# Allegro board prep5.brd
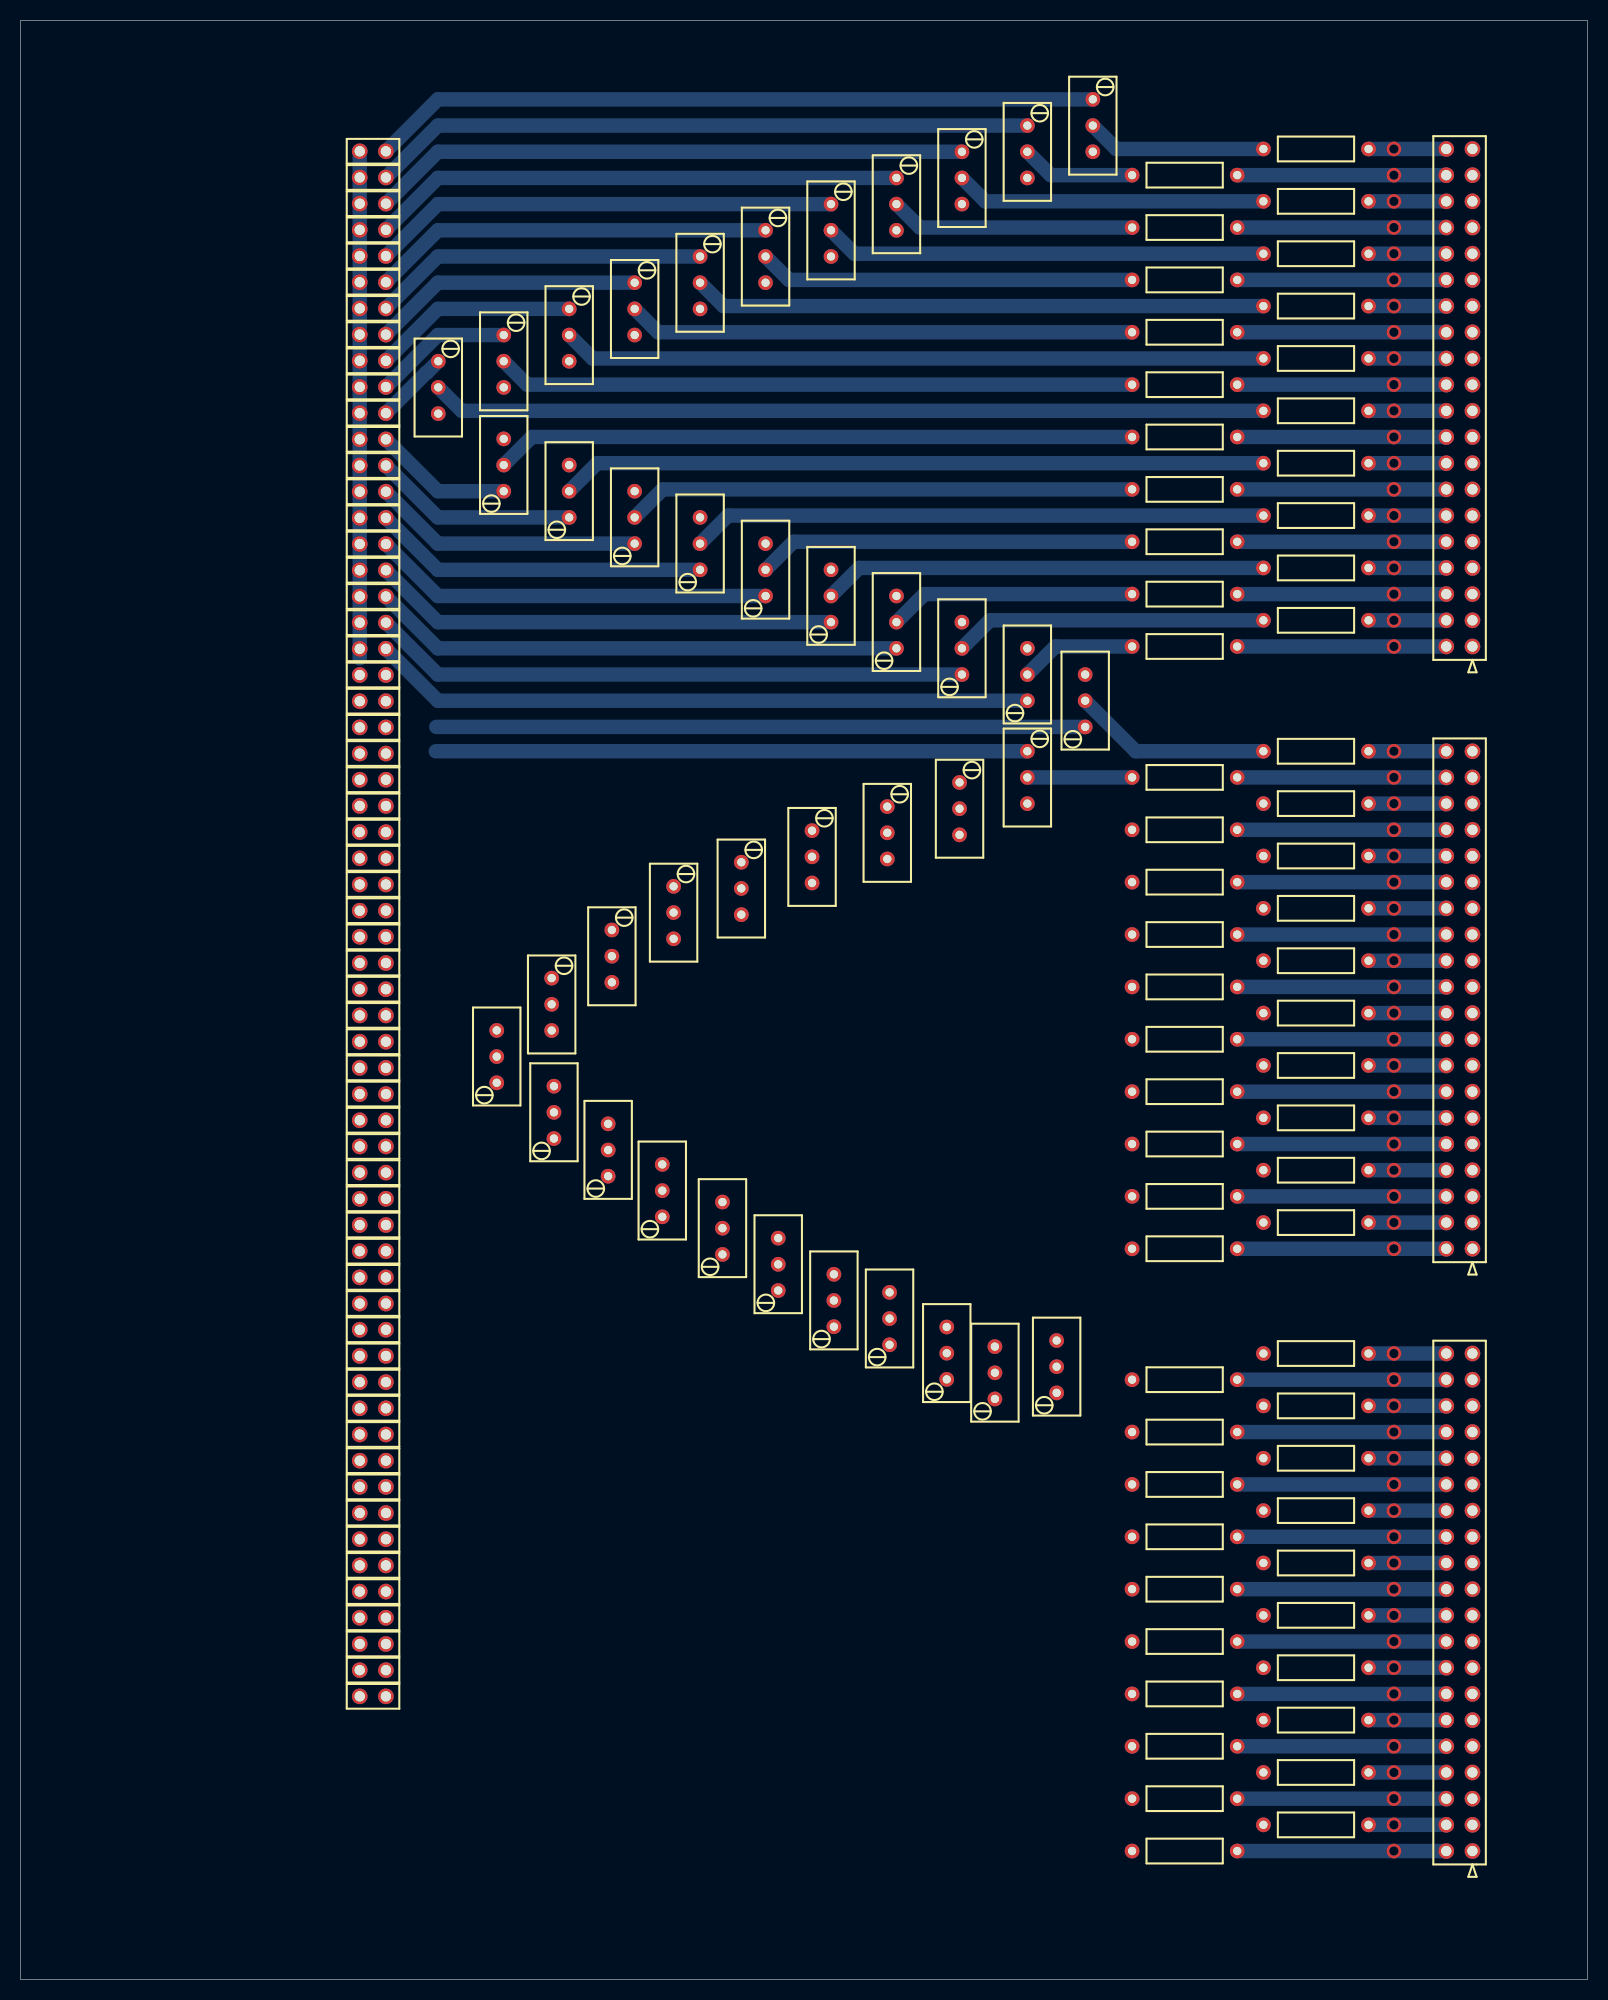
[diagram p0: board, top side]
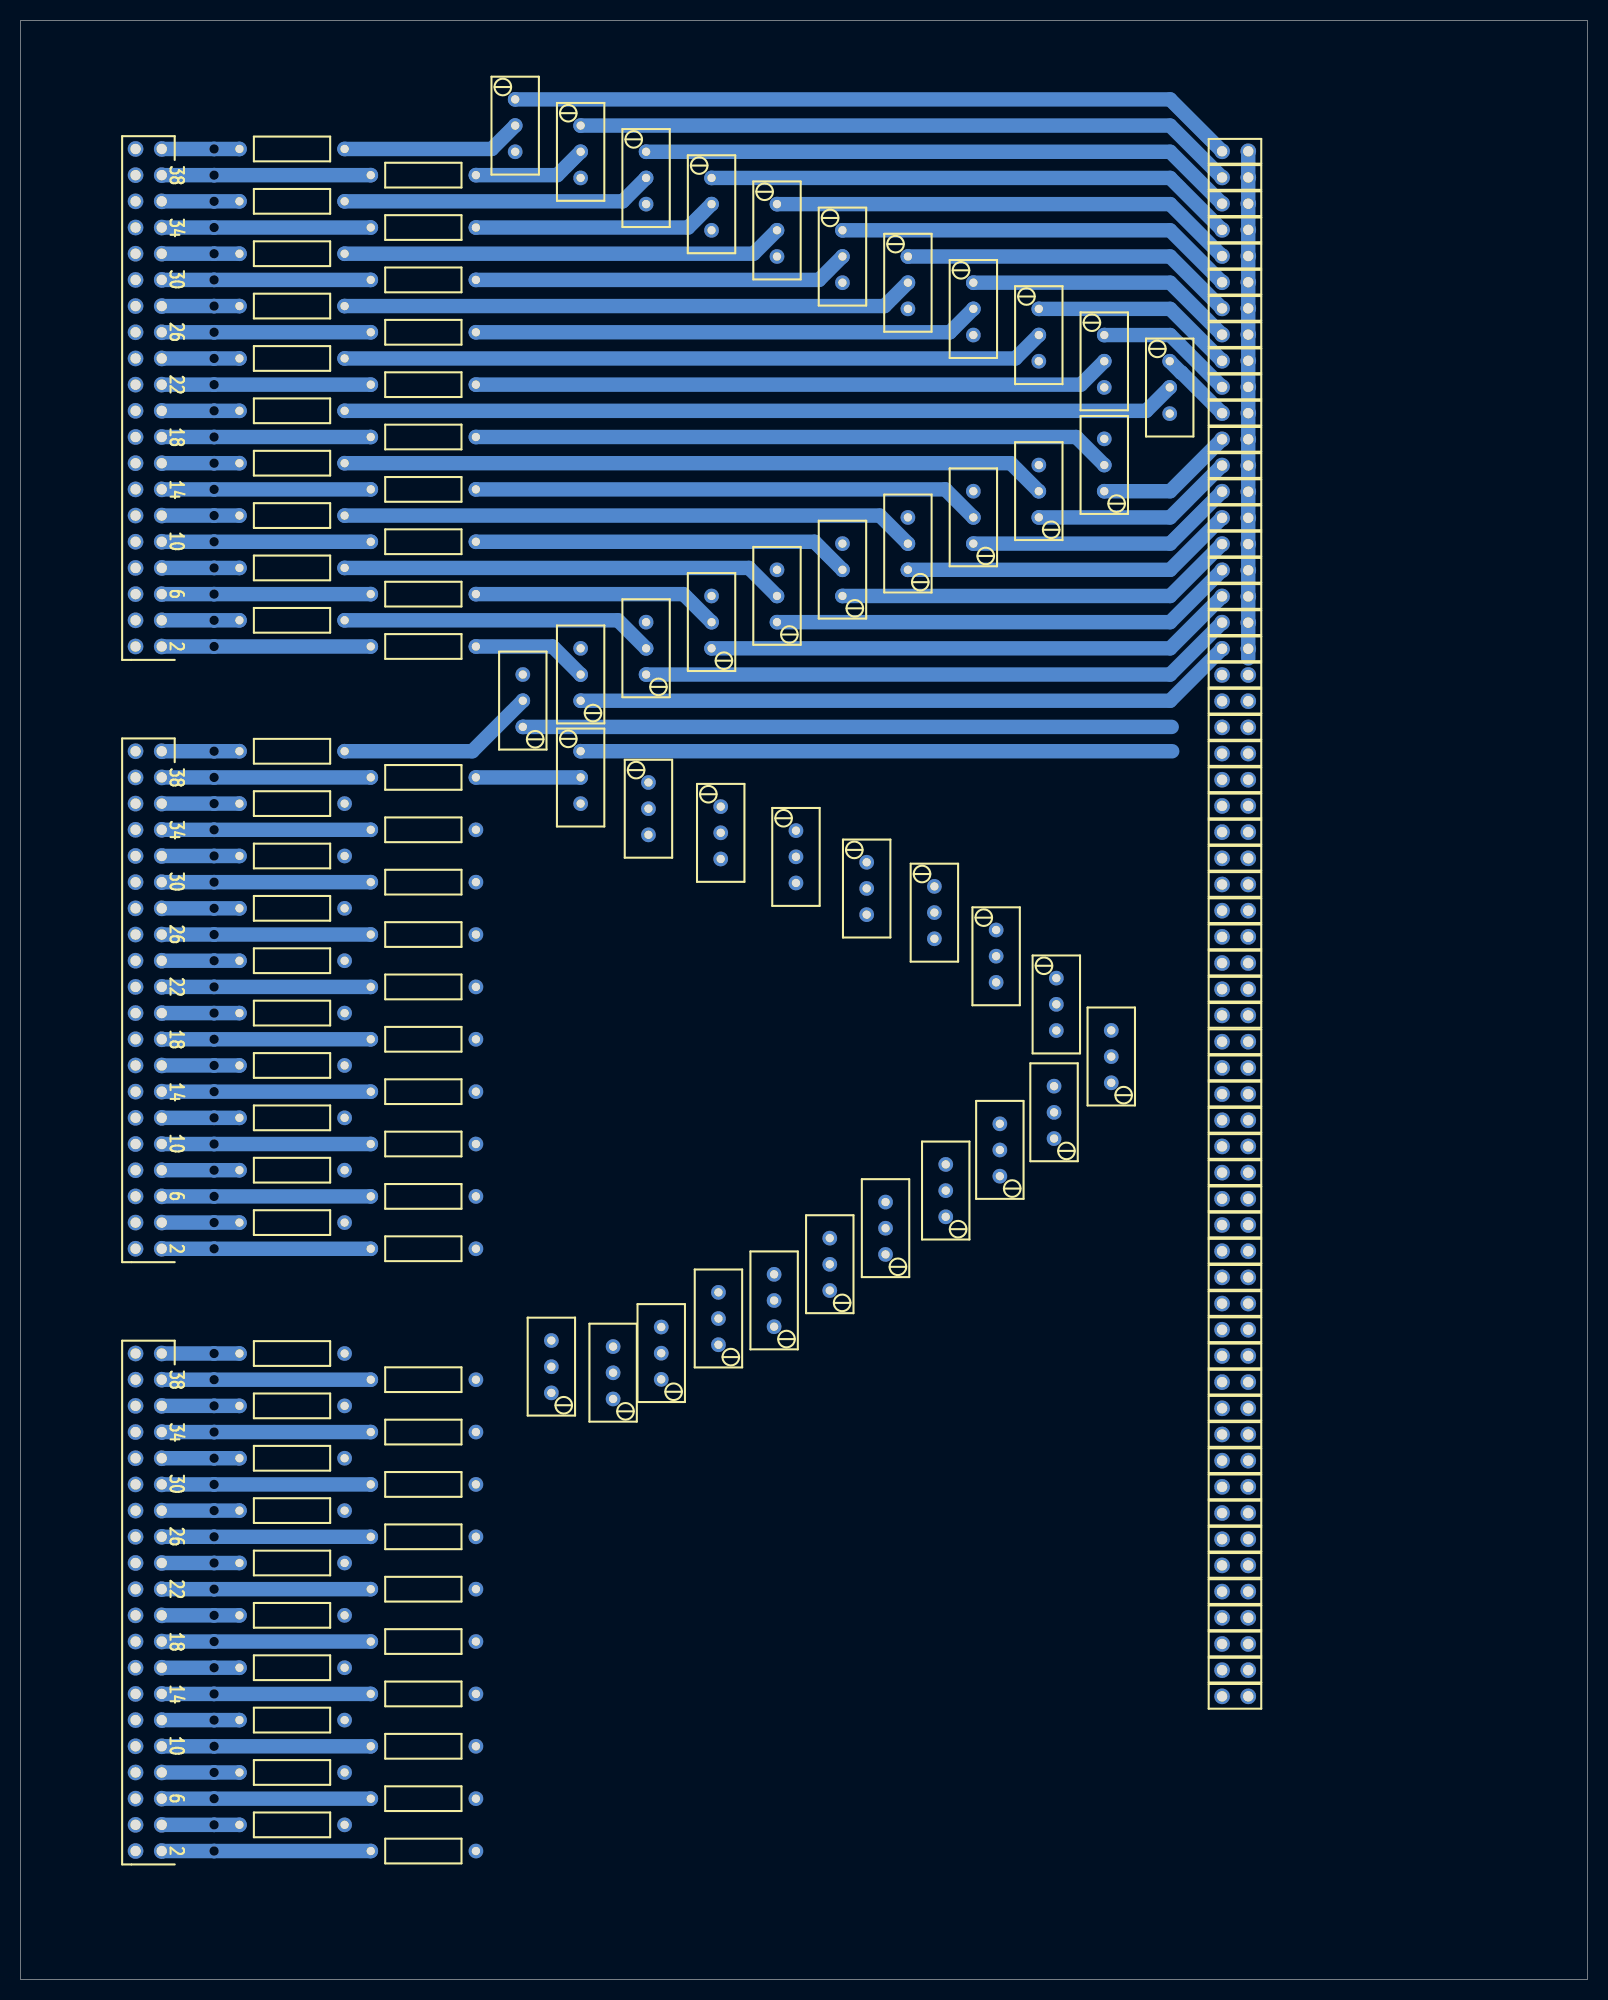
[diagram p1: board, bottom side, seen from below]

Outline 152 x 190 mm; copper layers: TOP, BOTTOM. Coordinates in mm from the lower left corner of the outline.
Outline path: 0,190 152,190 152,0 0,0 0,190

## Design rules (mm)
constraint set DEFAULT: min track width 0.15, pair gap 0.15

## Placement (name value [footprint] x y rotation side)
J1  -  [CONHE13D2X20M]  140.85 129.29 0 top
J2  -  [CONHE13D2X20M]  140.85 70.87 0 top
J3  -  [CONHE13D2X20M]  140.85 12.45 0 top
NOREF  -  []  0 0 90 top
NOREF#2  -  []  0 0 0 top
PO1  100  [POT45X95D]  104.02 182.36 270 top
PO2  100  [POT45X95D]  97.67 179.82 270 top
PO3  100  [POT45X95D]  91.32 177.28 270 top
PO4  100  [POT45X95D]  84.97 174.74 270 top
PO5  100  [POT45X95D]  78.62 172.2 270 top
PO6  100  [POT45X95D]  72.27 169.66 270 top
PO7  100  [POT45X95D]  65.92 167.12 270 top
PO8  100  [POT45X95D]  59.57 164.58 270 top
PO9  100  [POT45X95D]  53.22 162.04 270 top
PO10  100  [POT45X95D]  46.87 159.5 270 top
PO11  100  [POT45X95D]  40.52 156.96 270 top
PO12  100  [POT45X95D]  46.87 144.35 90 top
PO13  100  [POT45X95D]  53.22 141.81 90 top
PO14  100  [POT45X95D]  59.57 139.27 90 top
PO15  100  [POT45X95D]  65.92 136.73 90 top
PO16  100  [POT45X95D]  72.27 134.19 90 top
PO17  100  [POT45X95D]  78.62 131.65 90 top
PO18  100  [POT45X95D]  84.97 129.11 90 top
PO19  100  [POT45X95D]  91.32 126.57 90 top
PO20  100  [POT45X95D]  97.67 124.03 90 top
PO21  100  [POT45X95D]  103.28 121.49 90 top
PO22  100  [POT45X95D]  97.67 119.13 270 top
PO23  100  [POT45X95D]  91.09 116.1 270 top
PO24  100  [POT45X95D]  84.08 113.76 270 top
PO25  100  [POT45X95D]  76.78 111.43 270 top
PO26  100  [POT45X95D]  69.92 108.36 270 top
PO27  100  [POT45X95D]  63.35 106.02 270 top
PO28  100  [POT45X95D]  57.36 101.79 270 top
PO29  100  [POT45X95D]  51.52 97.12 270 top
PO30  100  [POT45X95D]  46.19 86.97 90 top
PO31  100  [POT45X95D]  51.74 81.56 90 top
PO32  100  [POT45X95D]  57 77.91 90 top
PO33  100  [POT45X95D]  62.25 73.97 90 top
PO34  100  [POT45X95D]  68.09 70.32 90 top
PO35  100  [POT45X95D]  73.5 66.82 90 top
PO36  100  [POT45X95D]  78.9 63.31 90 top
PO37  100  [POT45X95D]  84.3 61.56 90 top
PO38  100  [POT45X95D]  89.85 58.2 90 top
PO39  100  [POT45X95D]  94.52 56.3 90 top
PO40  100  [POT45X95D]  100.51 56.89 90 top
R1  100  [R100]  130.77 177.55 180 top
R2  100  [R100]  118.03 175.01 180 top
R3  100  [R100]  130.77 172.47 180 top
R4  100  [R100]  118.03 169.93 180 top
R5  100  [R100]  130.77 167.39 180 top
R6  100  [R100]  118.03 164.85 180 top
R7  100  [R100]  130.77 162.31 180 top
R8  100  [R100]  118.03 159.77 180 top
R9  100  [R100]  130.77 157.23 180 top
R10  100  [R100]  118.03 154.69 180 top
R11  100  [R100]  130.77 152.15 180 top
R12  100  [R100]  118.03 149.61 180 top
R13  100  [R100]  130.77 147.07 180 top
R14  100  [R100]  118.03 144.53 180 top
R15  100  [R100]  130.77 141.99 180 top
R16  100  [R100]  118.03 139.45 180 top
R17  100  [R100]  130.77 136.91 180 top
R18  100  [R100]  118.03 134.37 180 top
R19  100  [R100]  130.77 131.83 180 top
R20  100  [R100]  118.03 129.29 180 top
R21  100  [R100]  130.77 119.13 180 top
R22  100  [R100]  118.03 116.59 180 top
R23  100  [R100]  130.77 114.05 180 top
R24  100  [R100]  118.03 111.51 180 top
R25  100  [R100]  130.77 108.97 180 top
R26  100  [R100]  118.03 106.43 180 top
R27  100  [R100]  130.77 103.89 180 top
R28  100  [R100]  118.03 101.35 180 top
R29  100  [R100]  130.77 98.81 180 top
R30  100  [R100]  118.03 96.27 180 top
R31  100  [R100]  130.77 93.73 180 top
R32  100  [R100]  118.03 91.19 180 top
R33  100  [R100]  130.77 88.65 180 top
R34  100  [R100]  118.03 86.11 180 top
R35  100  [R100]  130.77 83.57 180 top
R36  100  [R100]  118.03 81.03 180 top
R37  100  [R100]  130.77 78.49 180 top
R38  100  [R100]  118.03 75.95 180 top
R39  100  [R100]  130.77 73.41 180 top
R40  100  [R100]  118.03 70.87 180 top
R41  100  [R100]  130.77 60.71 180 top
R42  100  [R100]  118.03 58.17 180 top
R43  100  [R100]  130.77 55.63 180 top
R44  100  [R100]  118.03 53.09 180 top
R45  100  [R100]  130.77 50.55 180 top
R46  100  [R100]  118.03 48.01 180 top
R47  100  [R100]  130.77 45.47 180 top
R48  100  [R100]  118.03 42.93 180 top
R49  100  [R100]  130.77 40.39 180 top
R50  100  [R100]  118.03 37.85 180 top
R51  100  [R100]  130.77 35.31 180 top
R52  100  [R100]  118.03 32.77 180 top
R53  100  [R100]  130.77 30.23 180 top
R54  100  [R100]  118.03 27.69 180 top
R55  100  [R100]  130.77 25.15 180 top
R56  100  [R100]  118.03 22.61 180 top
R57  100  [R100]  130.77 20.07 180 top
R58  100  [R100]  118.03 17.53 180 top
R59  100  [R100]  130.77 14.99 180 top
R60  100  [R100]  118.03 12.45 180 top
S1  -  [CONHE13D2M]  35.44 177.32 180 top
S2  -  [CONHE13D2M]  35.44 174.78 180 top
S3  -  [CONHE13D2M]  35.44 172.25 180 top
S4  -  [CONHE13D2M]  35.44 169.71 180 top
S5  -  [CONHE13D2M]  35.44 167.16 180 top
S6  -  [CONHE13D2M]  35.44 164.62 180 top
S7  -  [CONHE13D2M]  35.44 162.09 180 top
S8  -  [CONHE13D2M]  35.44 159.54 180 top
S9  -  [CONHE13D2M]  35.44 157 180 top
S10  -  [CONHE13D2M]  35.44 154.47 180 top
S11  -  [CONHE13D2M]  35.44 151.93 180 top
S12  -  [CONHE13D2M]  35.44 149.38 180 top
S13  -  [CONHE13D2M]  35.44 146.84 180 top
S14  -  [CONHE13D2M]  35.44 144.31 180 top
S15  -  [CONHE13D2M]  35.44 141.76 180 top
S16  -  [CONHE13D2M]  35.44 139.22 180 top
S17  -  [CONHE13D2M]  35.44 136.69 180 top
S18  -  [CONHE13D2M]  35.44 134.15 180 top
S19  -  [CONHE13D2M]  35.44 131.6 180 top
S20  -  [CONHE13D2M]  35.44 129.06 180 top
S21  -  [CONHE13D2M]  35.44 126.53 180 top
S22  -  [CONHE13D2M]  35.44 123.98 180 top
S23  -  [CONHE13D2M]  35.44 121.44 180 top
S24  -  [CONHE13D2M]  35.44 118.91 180 top
S25  -  [CONHE13D2M]  35.44 116.36 180 top
S26  -  [CONHE13D2M]  35.44 113.83 180 top
S27  -  [CONHE13D2M]  35.44 111.28 180 top
S28  -  [CONHE13D2M]  35.44 108.75 180 top
S29  -  [CONHE13D2M]  35.44 106.2 180 top
S30  -  [CONHE13D2M]  35.44 103.67 180 top
S31  -  [CONHE13D2M]  35.44 101.12 180 top
S32  -  [CONHE13D2M]  35.44 98.58 180 top
S33  -  [CONHE13D2M]  35.44 96.05 180 top
S34  -  [CONHE13D2M]  35.44 93.5 180 top
S35  -  [CONHE13D2M]  35.44 90.95 180 top
S36  -  [CONHE13D2M]  35.44 88.42 180 top
S37  -  [CONHE13D2M]  35.44 85.88 180 top
S38  -  [CONHE13D2M]  35.44 83.33 180 top
S39  -  [CONHE13D2M]  35.44 80.8 180 top
S40  -  [CONHE13D2M]  35.44 78.25 180 top
S41  -  [CONHE13D2M]  35.44 75.72 180 top
S42  -  [CONHE13D2M]  35.44 73.17 180 top
S43  -  [CONHE13D2M]  35.44 70.64 180 top
S44  -  [CONHE13D2M]  35.44 68.09 180 top
S45  -  [CONHE13D2M]  35.44 65.56 180 top
S46  -  [CONHE13D2M]  35.44 63.02 180 top
S47  -  [CONHE13D2M]  35.44 60.48 180 top
S48  -  [CONHE13D2M]  35.44 57.94 180 top
S49  -  [CONHE13D2M]  35.44 55.4 180 top
S50  -  [CONHE13D2M]  35.44 52.85 180 top
S51  -  [CONHE13D2M]  35.44 50.31 180 top
S52  -  [CONHE13D2M]  35.44 47.77 180 top
S53  -  [CONHE13D2M]  35.44 45.23 180 top
S54  -  [CONHE13D2M]  35.44 42.7 180 top
S55  -  [CONHE13D2M]  35.44 40.16 180 top
S56  -  [CONHE13D2M]  35.44 37.62 180 top
S57  -  [CONHE13D2M]  35.44 35.08 180 top
S58  -  [CONHE13D2M]  35.44 32.53 180 top
S59  -  [CONHE13D2M]  35.44 30 180 top
S60  -  [CONHE13D2M]  35.44 27.45 180 top

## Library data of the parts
J1-J3 = CON40P: part number: CON40P-HE13D
PO1-PO40 = POT: part number: POT-100,1/2W20T_D
R1-R60 = RGEN: part number: RGEN-100,M500MW5%
S1-S60 = STRAP: part number: STRAP-2X1

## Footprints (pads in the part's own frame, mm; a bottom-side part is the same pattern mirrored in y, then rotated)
CONHE13D2M
  round 1.52 hole 1: 1(0,0) 2(2.54,0)
CONHE13D2X20M
  round 1.52 hole 1: 1(0,0) 2(-2.54,0) 3(0,2.54) 4(-2.54,2.54) 5(0,5.08) 6(-2.54,5.08) 7(0,7.62) 8(-2.54,7.62) 9(0,10.16) 10(-2.54,10.16) 11(0,12.7) 12(-2.54,12.7) 13(0,15.24) 14(-2.54,15.24) 15(0,17.78) 16(-2.54,17.78) 17(0,20.32) 18(-2.54,20.32) 19(0,22.86) 20(-2.54,22.86) 21(0,25.4) 22(-2.54,25.4) 23(0,27.94) 24(-2.54,27.94) 25(0,30.48) 26(-2.54,30.48) 27(0,33.02) 28(-2.54,33.02) 29(0,35.56) 30(-2.54,35.56) 31(0,38.1) 32(-2.54,38.1) 33(0,40.64) 34(-2.54,40.64) 35(0,43.18) 36(-2.54,43.18) 37(0,45.72) 38(-2.54,45.72) 39(0,48.26) 40(-2.54,48.26)
POT45X95D
  round 1.43 hole 0.8: 1(0,0) 2(2.54,0) 3(5.08,0)
R100
  round 1.43 hole 0.8: 1(0,0) 2(10.2,0)

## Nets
GND: J1.1 J1.3 J1.5 J1.7 J1.9 J1.11 J1.13 J1.15 J1.17 J1.19 J1.21 J1.23 J1.25 J1.27 J1.29 J1.31 J1.33 J1.35 J1.37 J1.39 J2.1 J2.3 J2.5 J2.7 J2.9 J2.11 J2.13 J2.15 J2.17 J2.19 J2.21 J2.23 J2.25 J2.27 J2.29 J2.31 J2.33 J2.35 J2.37 J2.39 J3.1 J3.3 J3.5 J3.7 J3.9 J3.11 J3.13 J3.15 J3.17 J3.19 J3.21 J3.23 J3.25 J3.27 J3.29 J3.31 J3.33 J3.35 J3.37 J3.39
UNNAMED_1_CON40P_I1_A: J1.10(A<9>) R16.1
UNNAMED_1_CON40P_I1_A_1: J1.8 R17.1
UNNAMED_1_CON40P_I1_A_2: J1.6 R18.1
UNNAMED_1_CON40P_I1_A_3: J1.4 R19.1
UNNAMED_1_CON40P_I1_A_4: J1.40 R1.1
UNNAMED_1_CON40P_I1_A_5: J1.38 R2.1
UNNAMED_1_CON40P_I1_A_6: J1.36 R3.1
UNNAMED_1_CON40P_I1_A_7: J1.34 R4.1
UNNAMED_1_CON40P_I1_A_8: J1.32 R5.1
UNNAMED_1_CON40P_I1_A_9: J1.30 R6.1
UNNAMED_1_CON40P_I1_A_10: J1.28 R7.1
UNNAMED_1_CON40P_I1_A_11: J1.26 R8.1
UNNAMED_1_CON40P_I1_A_12: J1.24 R9.1
UNNAMED_1_CON40P_I1_A_13: J1.22 R10.1
UNNAMED_1_CON40P_I1_A_14: J1.2 R20.1
UNNAMED_1_CON40P_I1_A_15: J1.20 R11.1
UNNAMED_1_CON40P_I1_A_16: J1.18 R12.1
UNNAMED_1_CON40P_I1_A_17: J1.16 R13.1
UNNAMED_1_CON40P_I1_A_18: J1.14 R14.1
UNNAMED_1_CON40P_I1_A_19: J1.12 R15.1
UNNAMED_1_CON40P_I2_A: J3.28 R47.1
UNNAMED_1_CON40P_I2_A_1: J3.30 R46.1
UNNAMED_1_CON40P_I2_A_2: J3.38 R42.1
UNNAMED_1_CON40P_I2_A_3: J3.32 R45.1
UNNAMED_1_CON40P_I2_A_4: J3.34 R44.1
UNNAMED_1_CON40P_I2_A_5: J3.36 R43.1
UNNAMED_1_CON40P_I2_A_6: J3.40 R41.1
UNNAMED_1_CON40P_I2_A_7: J3.6 R58.1
UNNAMED_1_CON40P_I2_A_8: J3.8 R57.1
UNNAMED_1_CON40P_I2_A_9: J3.4 R59.1
UNNAMED_1_CON40P_I2_A_10: J3.2 R60.1
UNNAMED_1_CON40P_I2_A_11: J3.10(A<9>) R56.1
UNNAMED_1_CON40P_I2_A_12: J3.12 R55.1
UNNAMED_1_CON40P_I2_A_13: J3.14 R54.1
UNNAMED_1_CON40P_I2_A_14: J3.16 R53.1
UNNAMED_1_CON40P_I2_A_15: J3.18 R52.1
UNNAMED_1_CON40P_I2_A_16: J3.20 R51.1
UNNAMED_1_CON40P_I2_A_17: J3.22 R50.1
UNNAMED_1_CON40P_I2_A_18: J3.24 R49.1
UNNAMED_1_CON40P_I2_A_19: J3.26 R48.1
UNNAMED_1_CON40P_I3_A: J2.28 R27.1
UNNAMED_1_CON40P_I3_A_1: J2.30 R26.1
UNNAMED_1_CON40P_I3_A_2: J2.38 R22.1
UNNAMED_1_CON40P_I3_A_3: J2.32 R25.1
UNNAMED_1_CON40P_I3_A_4: J2.34 R24.1
UNNAMED_1_CON40P_I3_A_5: J2.36 R23.1
UNNAMED_1_CON40P_I3_A_6: J2.40 R21.1
UNNAMED_1_CON40P_I3_A_7: J2.6 R38.1
UNNAMED_1_CON40P_I3_A_8: J2.8 R37.1
UNNAMED_1_CON40P_I3_A_9: J2.4 R39.1
UNNAMED_1_CON40P_I3_A_10: J2.2 R40.1
UNNAMED_1_CON40P_I3_A_11: J2.10(A<9>) R36.1
UNNAMED_1_CON40P_I3_A_12: J2.12 R35.1
UNNAMED_1_CON40P_I3_A_13: J2.14 R34.1
UNNAMED_1_CON40P_I3_A_14: J2.16 R33.1
UNNAMED_1_CON40P_I3_A_15: J2.18 R32.1
UNNAMED_1_CON40P_I3_A_16: J2.20 R31.1
UNNAMED_1_CON40P_I3_A_17: J2.22 R30.1
UNNAMED_1_CON40P_I3_A_18: J2.24 R29.1
UNNAMED_1_CON40P_I3_A_19: J2.26 R28.1
UNNAMED_1_POT_I5_A: PO1.1 S1.1
UNNAMED_1_POT_I5_B: PO1.2 R1.2(B<0>)
UNNAMED_1_POT_I7_A: PO2.1 S2.1
UNNAMED_1_POT_I7_B: PO2.2 R2.2(B<0>)
UNNAMED_1_POT_I26_A: PO3.1 S3.1
UNNAMED_1_POT_I26_B: PO3.2 R3.2(B<0>)
UNNAMED_1_POT_I27_A: PO4.1 S4.1
UNNAMED_1_POT_I27_B: PO4.2 R4.2(B<0>)
UNNAMED_1_POT_I28_A: PO5.1 S5.1
UNNAMED_1_POT_I28_B: PO5.2 R5.2(B<0>)
UNNAMED_1_POT_I29_A: PO6.1 S6.1
UNNAMED_1_POT_I29_B: PO6.2 R6.2(B<0>)
UNNAMED_1_POT_I30_A: PO7.1 S7.1
UNNAMED_1_POT_I30_B: PO7.2 R7.2(B<0>)
UNNAMED_1_POT_I31_A: PO8.1 S8.1
UNNAMED_1_POT_I31_B: PO8.2 R8.2(B<0>)
UNNAMED_1_POT_I32_A: PO9.1 S9.1
UNNAMED_1_POT_I32_B: PO9.2 R9.2(B<0>)
UNNAMED_1_POT_I33_A: PO10.1 S10.1
UNNAMED_1_POT_I33_B: PO10.2 R10.2(B<0>)
UNNAMED_1_POT_I34_A: PO11.1 S11.1
UNNAMED_1_POT_I34_B: PO11.2 R11.2(B<0>)
UNNAMED_1_POT_I35_A: PO12.1 S12.1
UNNAMED_1_POT_I35_B: PO12.2 R12.2(B<0>)
UNNAMED_1_POT_I36_A: PO13.1 S13.1
UNNAMED_1_POT_I36_B: PO13.2 R13.2(B<0>)
UNNAMED_1_POT_I37_A: PO14.1 S14.1
UNNAMED_1_POT_I37_B: PO14.2 R14.2(B<0>)
UNNAMED_1_POT_I38_A: PO15.1 S15.1
UNNAMED_1_POT_I38_B: PO15.2 R15.2(B<0>)
UNNAMED_1_POT_I39_A: PO16.1 S16.1
UNNAMED_1_POT_I39_B: PO16.2 R16.2(B<0>)
UNNAMED_1_POT_I40_A: PO17.1 S17.1
UNNAMED_1_POT_I40_B: PO17.2 R17.2(B<0>)
UNNAMED_1_POT_I41_A: PO18.1 S18.1
UNNAMED_1_POT_I41_B: PO18.2 R18.2(B<0>)
UNNAMED_1_POT_I42_A: PO19.1 S19.1
UNNAMED_1_POT_I42_B: PO19.2 R19.2(B<0>)
UNNAMED_1_POT_I43_A: PO20.1 S20.1
UNNAMED_1_POT_I43_B: PO20.2 R20.2(B<0>)
UNNAMED_1_POT_I44_A: PO40.1 S40.1
UNNAMED_1_POT_I44_B: PO40.2 R40.2(B<0>)
UNNAMED_1_POT_I45_A: PO39.1 S39.1
UNNAMED_1_POT_I45_B: PO39.2 R39.2(B<0>)
UNNAMED_1_POT_I46_A: PO38.1 S38.1
UNNAMED_1_POT_I46_B: PO38.2 R38.2(B<0>)
UNNAMED_1_POT_I47_A: PO33.1 S33.1
UNNAMED_1_POT_I47_B: PO33.2 R33.2(B<0>)
UNNAMED_1_POT_I48_A: PO32.1 S32.1
UNNAMED_1_POT_I48_B: PO32.2 R32.2(B<0>)
UNNAMED_1_POT_I49_A: PO31.1 S31.1
UNNAMED_1_POT_I49_B: PO31.2 R31.2(B<0>)
UNNAMED_1_POT_I50_A: PO30.1 S30.1
UNNAMED_1_POT_I50_B: PO30.2 R30.2(B<0>)
UNNAMED_1_POT_I51_A: PO29.1 S29.1
UNNAMED_1_POT_I51_B: PO29.2 R29.2(B<0>)
UNNAMED_1_POT_I52_A: PO27.1 S27.1
UNNAMED_1_POT_I52_B: PO27.2 R27.2(B<0>)
UNNAMED_1_POT_I53_A: PO28.1 S28.1
UNNAMED_1_POT_I53_B: PO28.2 R28.2(B<0>)
UNNAMED_1_POT_I54_A: PO26.1 S26.1
UNNAMED_1_POT_I54_B: PO26.2 R26.2(B<0>)
UNNAMED_1_POT_I55_A: PO25.1 S25.1
UNNAMED_1_POT_I55_B: PO25.2 R25.2(B<0>)
UNNAMED_1_POT_I56_A: PO24.1 S24.1
UNNAMED_1_POT_I56_B: PO24.2 R24.2(B<0>)
UNNAMED_1_POT_I57_A: PO22.1 S22.1
UNNAMED_1_POT_I57_B: PO22.2 R22.2(B<0>)
UNNAMED_1_POT_I58_A: PO21.1 S21.1
UNNAMED_1_POT_I58_B: PO21.2 R21.2(B<0>)
UNNAMED_1_POT_I59_A: PO23.1 S23.1
UNNAMED_1_POT_I59_B: PO23.2 R23.2(B<0>)
UNNAMED_1_POT_I72_A: PO37.1 S37.1
UNNAMED_1_POT_I72_B: PO37.2 R37.2(B<0>)
UNNAMED_1_POT_I73_A: PO36.1 S36.1
UNNAMED_1_POT_I73_B: PO36.2 R36.2(B<0>)
UNNAMED_1_POT_I74_A: PO35.1 S35.1
UNNAMED_1_POT_I74_B: PO35.2 R35.2(B<0>)
UNNAMED_1_POT_I75_A: PO34.1 S34.1
UNNAMED_1_POT_I75_B: PO34.2 R34.2(B<0>)
UNNAMED_1_POT_I84_A: S60.1
UNNAMED_1_POT_I84_B: R60.2(B<0>)
UNNAMED_1_POT_I85_A: S59.1
UNNAMED_1_POT_I85_B: R59.2(B<0>)
UNNAMED_1_POT_I86_A: S58.1
UNNAMED_1_POT_I86_B: R58.2(B<0>)
UNNAMED_1_POT_I87_A: S53.1
UNNAMED_1_POT_I87_B: R53.2(B<0>)
UNNAMED_1_POT_I88_A: S52.1
UNNAMED_1_POT_I88_B: R52.2(B<0>)
UNNAMED_1_POT_I89_A: S51.1
UNNAMED_1_POT_I89_B: R51.2(B<0>)
UNNAMED_1_POT_I90_A: S50.1
UNNAMED_1_POT_I90_B: R50.2(B<0>)
UNNAMED_1_POT_I91_A: S49.1
UNNAMED_1_POT_I91_B: R49.2(B<0>)
UNNAMED_1_POT_I92_A: S47.1
UNNAMED_1_POT_I92_B: R47.2(B<0>)
UNNAMED_1_POT_I93_A: S48.1
UNNAMED_1_POT_I93_B: R48.2(B<0>)
UNNAMED_1_POT_I94_A: S46.1
UNNAMED_1_POT_I94_B: R46.2(B<0>)
UNNAMED_1_POT_I95_A: S45.1
UNNAMED_1_POT_I95_B: R45.2(B<0>)
UNNAMED_1_POT_I96_A: S44.1
UNNAMED_1_POT_I96_B: R44.2(B<0>)
UNNAMED_1_POT_I97_A: S42.1
UNNAMED_1_POT_I97_B: R42.2(B<0>)
UNNAMED_1_POT_I98_A: S41.1
UNNAMED_1_POT_I98_B: R41.2(B<0>)
UNNAMED_1_POT_I99_A: S43.1
UNNAMED_1_POT_I99_B: R43.2(B<0>)
UNNAMED_1_POT_I112_A: S57.1
UNNAMED_1_POT_I112_B: R57.2(B<0>)
UNNAMED_1_POT_I113_A: S56.1
UNNAMED_1_POT_I113_B: R56.2(B<0>)
UNNAMED_1_POT_I114_A: S55.1
UNNAMED_1_POT_I114_B: R55.2(B<0>)
UNNAMED_1_POT_I115_A: S54.1
UNNAMED_1_POT_I115_B: R54.2(B<0>)
UNNAMED_1_STRAP_I125_B: S1.2(B) S2.2(B) S3.2(B) S4.2(B) S5.2(B) S6.2(B) S7.2(B) S8.2(B) S9.2(B) S10.2(B) S11.2(B) S12.2(B) S13.2(B) S14.2(B) S15.2(B) S16.2(B) S17.2(B) S18.2(B) S19.2(B) S20.2(B)
UNNAMED_1_STRAP_I145_B: S21.2(B) S22.2(B) S23.2(B) S24.2(B) S25.2(B) S26.2(B) S27.2(B) S28.2(B) S29.2(B) S30.2(B) S31.2(B) S32.2(B) S33.2(B) S34.2(B) S35.2(B) S36.2(B) S37.2(B) S38.2(B) S39.2(B) S40.2(B)
UNNAMED_1_STRAP_I165_B: S41.2(B) S42.2(B) S43.2(B) S44.2(B) S45.2(B) S46.2(B) S47.2(B) S48.2(B) S49.2(B) S50.2(B) S51.2(B) S52.2(B) S53.2(B) S54.2(B) S55.2(B) S56.2(B) S57.2(B) S58.2(B) S59.2(B) S60.2(B)

Pads without a net: PO1 3; PO2 3; PO3 3; PO4 3; PO5 3; PO6 3; PO7 3; PO8 3; PO9 3; PO10 3; PO11 3; PO12 3; PO13 3; PO14 3; PO15 3; PO16 3; PO17 3; PO18 3; PO19 3; PO20 3; PO21 3; PO22 3; PO23 3; PO24 3; PO25 3; PO26 3; PO27 3; PO28 3; PO29 3; PO30 3; PO31 3; PO32 3; PO33 3; PO34 3; PO35 3; PO36 3; PO37 3; PO38 3; PO39 3; PO40 3

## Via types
v1: diameter 1.42, hole 0.9, TOP to BOTTOM, 60 vias

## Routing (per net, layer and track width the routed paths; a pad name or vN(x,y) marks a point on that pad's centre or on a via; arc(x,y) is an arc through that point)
UNNAMED_1_CON40P_I1_A: length 20.3
  BOTTOM w1.4: R16.1 v1(133.23,139.45) J1.10
UNNAMED_1_CON40P_I1_A_1: length 7.5
  BOTTOM w1.4: R17.1 v1(133.23,136.91) J1.8
UNNAMED_1_CON40P_I1_A_2: length 20.3
  BOTTOM w1.4: J1.6 v1(133.23,134.37) R18.1
UNNAMED_1_CON40P_I1_A_3: length 7.5
  BOTTOM w1.4: R19.1 v1(133.23,131.83) J1.4
UNNAMED_1_CON40P_I1_A_4: length 7.5
  BOTTOM w1.4: R1.1 v1(133.23,177.55) J1.40
UNNAMED_1_CON40P_I1_A_5: length 20.3
  BOTTOM w1.4: J1.38 v1(133.23,175.01) R2.1
UNNAMED_1_CON40P_I1_A_6: length 7.5
  BOTTOM w1.4: J1.36 v1(133.23,172.47) R3.1
UNNAMED_1_CON40P_I1_A_7: length 20.3
  BOTTOM w1.4: R4.1 v1(133.23,169.93) J1.34
UNNAMED_1_CON40P_I1_A_8: length 7.5
  BOTTOM w1.4: J1.32 v1(133.23,167.39) R5.1
UNNAMED_1_CON40P_I1_A_9: length 20.3
  BOTTOM w1.4: R6.1 v1(133.23,164.85) J1.30
UNNAMED_1_CON40P_I1_A_10: length 7.5
  BOTTOM w1.4: J1.28 v1(133.23,162.31) R7.1
UNNAMED_1_CON40P_I1_A_11: length 20.3
  BOTTOM w1.4: J1.26 v1(133.23,159.77) R8.1
UNNAMED_1_CON40P_I1_A_12: length 7.5
  BOTTOM w1.4: R9.1 v1(133.23,157.23) J1.24
UNNAMED_1_CON40P_I1_A_13: length 20.3
  BOTTOM w1.4: J1.22 v1(133.23,154.69) R10.1
UNNAMED_1_CON40P_I1_A_14: length 20.3
  BOTTOM w1.4: J1.2 v1(133.23,129.29) R20.1
UNNAMED_1_CON40P_I1_A_15: length 7.5
  BOTTOM w1.4: J1.20 v1(133.23,152.15) R11.1
UNNAMED_1_CON40P_I1_A_16: length 20.3
  BOTTOM w1.4: J1.18 v1(133.23,149.61) R12.1
UNNAMED_1_CON40P_I1_A_17: length 7.5
  BOTTOM w1.4: R13.1 v1(133.23,147.07) J1.16
UNNAMED_1_CON40P_I1_A_18: length 20.3
  BOTTOM w1.4: R14.1 v1(133.23,144.53) J1.14
UNNAMED_1_CON40P_I1_A_19: length 7.5
  BOTTOM w1.4: R15.1 v1(133.23,141.99) J1.12
UNNAMED_1_CON40P_I2_A: length 7.5
  BOTTOM w1.4: J3.28 v1(133.23,45.47) R47.1
UNNAMED_1_CON40P_I2_A_1: length 20.3
  BOTTOM w1.4: R46.1 v1(133.23,48.01) J3.30
UNNAMED_1_CON40P_I2_A_2: length 20.3
  BOTTOM w1.4: J3.38 v1(133.23,58.17) R42.1
UNNAMED_1_CON40P_I2_A_3: length 7.5
  BOTTOM w1.4: J3.32 v1(133.23,50.55) R45.1
UNNAMED_1_CON40P_I2_A_4: length 20.3
  BOTTOM w1.4: R44.1 v1(133.23,53.09) J3.34
UNNAMED_1_CON40P_I2_A_5: length 7.5
  BOTTOM w1.4: J3.36 v1(133.23,55.63) R43.1
UNNAMED_1_CON40P_I2_A_6: length 7.5
  BOTTOM w1.4: J3.40 v1(133.23,60.71) R41.1
UNNAMED_1_CON40P_I2_A_7: length 20.3
  BOTTOM w1.4: J3.6 v1(133.23,17.53) R58.1
UNNAMED_1_CON40P_I2_A_8: length 7.5
  BOTTOM w1.4: R57.1 v1(133.23,20.07) J3.8
UNNAMED_1_CON40P_I2_A_9: length 7.5
  BOTTOM w1.4: R59.1 v1(133.23,14.99) J3.4
UNNAMED_1_CON40P_I2_A_10: length 20.3
  BOTTOM w1.4: R60.1 v1(133.23,12.45) J3.2
UNNAMED_1_CON40P_I2_A_11: length 20.3
  BOTTOM w1.4: R56.1 v1(133.23,22.61) J3.10
UNNAMED_1_CON40P_I2_A_12: length 7.5
  BOTTOM w1.4: J3.12 v1(133.23,25.15) R55.1
UNNAMED_1_CON40P_I2_A_13: length 20.3
  BOTTOM w1.4: R54.1 v1(133.23,27.69) J3.14
UNNAMED_1_CON40P_I2_A_14: length 7.5
  BOTTOM w1.4: R53.1 v1(133.23,30.23) J3.16
UNNAMED_1_CON40P_I2_A_15: length 20.3
  BOTTOM w1.4: J3.18 v1(133.23,32.77) R52.1
UNNAMED_1_CON40P_I2_A_16: length 7.5
  BOTTOM w1.4: R51.1 v1(133.23,35.31) J3.20
UNNAMED_1_CON40P_I2_A_17: length 20.3
  BOTTOM w1.4: R50.1 v1(133.23,37.85) J3.22
UNNAMED_1_CON40P_I2_A_18: length 7.5
  BOTTOM w1.4: J3.24 v1(133.23,40.39) R49.1
UNNAMED_1_CON40P_I2_A_19: length 20.3
  BOTTOM w1.4: R48.1 v1(133.23,42.93) J3.26
UNNAMED_1_CON40P_I3_A: length 7.5
  BOTTOM w1.4: R27.1 v1(133.23,103.89) J2.28
UNNAMED_1_CON40P_I3_A_1: length 20.3
  BOTTOM w1.4: J2.30 v1(133.23,106.43) R26.1
UNNAMED_1_CON40P_I3_A_2: length 20.3
  BOTTOM w1.4: R22.1 v1(133.23,116.59) J2.38
UNNAMED_1_CON40P_I3_A_3: length 7.5
  BOTTOM w1.4: R25.1 v1(133.23,108.97) J2.32
UNNAMED_1_CON40P_I3_A_4: length 20.3
  BOTTOM w1.4: R24.1 v1(133.23,111.51) J2.34
UNNAMED_1_CON40P_I3_A_5: length 7.5
  BOTTOM w1.4: R23.1 v1(133.23,114.05) J2.36
UNNAMED_1_CON40P_I3_A_6: length 7.5
  BOTTOM w1.4: J2.40 v1(133.23,119.13) R21.1
UNNAMED_1_CON40P_I3_A_7: length 20.3
  BOTTOM w1.4: J2.6 v1(133.23,75.95) R38.1
UNNAMED_1_CON40P_I3_A_8: length 7.5
  BOTTOM w1.4: J2.8 v1(133.23,78.49) R37.1
UNNAMED_1_CON40P_I3_A_9: length 7.5
  BOTTOM w1.4: R39.1 v1(133.23,73.41) J2.4
UNNAMED_1_CON40P_I3_A_10: length 20.3
  BOTTOM w1.4: J2.2 v1(133.23,70.87) R40.1
UNNAMED_1_CON40P_I3_A_11: length 20.3
  BOTTOM w1.4: J2.10 v1(133.23,81.03) R36.1
UNNAMED_1_CON40P_I3_A_12: length 7.5
  BOTTOM w1.4: J2.12 v1(133.23,83.57) R35.1
UNNAMED_1_CON40P_I3_A_13: length 20.3
  BOTTOM w1.4: J2.14 v1(133.23,86.11) R34.1
UNNAMED_1_CON40P_I3_A_14: length 7.5
  BOTTOM w1.4: J2.16 v1(133.23,88.65) R33.1
UNNAMED_1_CON40P_I3_A_15: length 20.3
  BOTTOM w1.4: R32.1 v1(133.23,91.19) J2.18
UNNAMED_1_CON40P_I3_A_16: length 7.5
  BOTTOM w1.4: J2.20 v1(133.23,93.73) R31.1
UNNAMED_1_CON40P_I3_A_17: length 20.3
  BOTTOM w1.4: R30.1 v1(133.23,96.27) J2.22
UNNAMED_1_CON40P_I3_A_18: length 7.5
  BOTTOM w1.4: J2.24 v1(133.23,98.81) R29.1
UNNAMED_1_CON40P_I3_A_19: length 20.3
  BOTTOM w1.4: J2.26 v1(133.23,101.35) R28.1
UNNAMED_1_POT_I5_A: length 70.7
  BOTTOM w1.4: S1.1 40.48,182.36 PO1.1
UNNAMED_1_POT_I5_B: length 17.5
  BOTTOM w1.4: R1.2 106.29,177.55 PO1.2
UNNAMED_1_POT_I7_A: length 64.3
  BOTTOM w1.4: PO2.1 40.48,179.82 S2.1
UNNAMED_1_POT_I7_B: length 11.1
  BOTTOM w1.4: PO2.2 99.94,175.01 R2.2
UNNAMED_1_POT_I26_A: length 58
  BOTTOM w1.4: PO3.1 40.48,177.28 S3.1
UNNAMED_1_POT_I26_B: length 30.2
  BOTTOM w1.4: PO3.2 93.59,172.47 R3.2
UNNAMED_1_POT_I27_A: length 51.6
  BOTTOM w1.4: PO4.1 40.48,174.74 S4.1
UNNAMED_1_POT_I27_B: length 23.8
  BOTTOM w1.4: R4.2 87.24,169.93 PO4.2
UNNAMED_1_POT_I28_A: length 45.3
  BOTTOM w1.4: PO5.1 40.48,172.2 S5.1
UNNAMED_1_POT_I28_B: length 42.9
  BOTTOM w1.4: R5.2 80.89,167.39 PO5.2
UNNAMED_1_POT_I29_A: length 38.9
  BOTTOM w1.4: S6.1 40.48,169.66 PO6.1
UNNAMED_1_POT_I29_B: length 36.5
  BOTTOM w1.4: R6.2 74.54,164.85 PO6.2
UNNAMED_1_POT_I30_A: length 32.6
  BOTTOM w1.4: S7.1 40.48,167.12 PO7.1
UNNAMED_1_POT_I30_B: length 55.6
  BOTTOM w1.4: R7.2 68.19,162.31 PO7.2
UNNAMED_1_POT_I31_A: length 26.2
  BOTTOM w1.4: PO8.1 40.48,164.58 S8.1
UNNAMED_1_POT_I31_B: length 49.2
  BOTTOM w1.4: R8.2 61.84,159.77 PO8.2
UNNAMED_1_POT_I32_A: length 19.9
  BOTTOM w1.4: S9.1 40.48,162.04 PO9.1
UNNAMED_1_POT_I32_B: length 68.3
  BOTTOM w1.4: PO9.2 55.49,157.23 R9.2
UNNAMED_1_POT_I33_A: length 13.5
  BOTTOM w1.4: S10.1 40.48,159.5 PO10.1
UNNAMED_1_POT_I33_B: length 61.9
  BOTTOM w1.4: PO10.2 49.14,154.69 R10.2
UNNAMED_1_POT_I34_A: length 7.2
  BOTTOM w1.4: S11.1 39.37,155.85 39.41,155.85 PO11.1
UNNAMED_1_POT_I34_B: length 81
  BOTTOM w1.4: R11.2 42.79,152.15 PO11.2
UNNAMED_1_POT_I35_A: length 13.5
  BOTTOM w1.4: S12.1 40.48,144.35 PO12.1
UNNAMED_1_POT_I35_B: length 62.1
  BOTTOM w1.4: R12.2 49.59,149.61 PO12.2
UNNAMED_1_POT_I36_A: length 19.9
  BOTTOM w1.4: PO13.1 40.48,141.81 S13.1
UNNAMED_1_POT_I36_B: length 68.5
  BOTTOM w1.4: PO13.2 55.94,147.07 R13.2
UNNAMED_1_POT_I37_A: length 26.2
  BOTTOM w1.4: PO14.1 40.48,139.27 S14.1
UNNAMED_1_POT_I37_B: length 49.4
  BOTTOM w1.4: R14.2 62.29,144.53 PO14.2
UNNAMED_1_POT_I38_A: length 32.6
  BOTTOM w1.4: PO15.1 40.48,136.73 S15.1
UNNAMED_1_POT_I38_B: length 55.8
  BOTTOM w1.4: R15.2 68.64,141.99 PO15.2
UNNAMED_1_POT_I39_A: length 38.9
  BOTTOM w1.4: S16.1 40.48,134.19 PO16.1
UNNAMED_1_POT_I39_B: length 36.7
  BOTTOM w1.4: PO16.2 74.99,139.45 R16.2
UNNAMED_1_POT_I40_A: length 45.3
  BOTTOM w1.4: S17.1 40.48,131.65 PO17.1
UNNAMED_1_POT_I40_B: length 43.1
  BOTTOM w1.4: R17.2 81.34,136.91 PO17.2
UNNAMED_1_POT_I41_A: length 51.6
  BOTTOM w1.4: PO18.1 40.48,129.11 S18.1
UNNAMED_1_POT_I41_B: length 24
  BOTTOM w1.4: PO18.2 87.69,134.37 R18.2
UNNAMED_1_POT_I42_A: length 58
  BOTTOM w1.4: S19.1 40.48,126.57 PO19.1
UNNAMED_1_POT_I42_B: length 30.4
  BOTTOM w1.4: PO19.2 94.04,131.83 R19.2
UNNAMED_1_POT_I43_A: length 64.3
  BOTTOM w1.4: PO20.1 40.48,124.03 S20.1
UNNAMED_1_POT_I43_B: length 11.3
  BOTTOM w1.4: PO20.2 100.39,129.29 R20.2
UNNAMED_1_POT_I57_A: length 57.4
  BOTTOM w1.4: 40.28,119.13 PO22.1
UNNAMED_1_POT_I57_B: length 10.2
  BOTTOM w1.4: R22.2 PO22.2
UNNAMED_1_POT_I58_A: length 63
  BOTTOM w1.4: PO21.1 40.33,121.49
UNNAMED_1_POT_I58_B: length 19.3
  BOTTOM w1.4: PO21.2 108.18,119.13 R21.2
UNNAMED_1_STRAP_I125_B: length 49.2
  BOTTOM w1.4: 32.9,128.13 S20.2 S19.2 S18.2 S17.2 S16.2 S15.2 S14.2 S13.2 S12.2 S11.2 S10.2 S9.2 S8.2 S7.2 S6.2 S5.2 S4.2 S3.2 S2.2 S1.2
